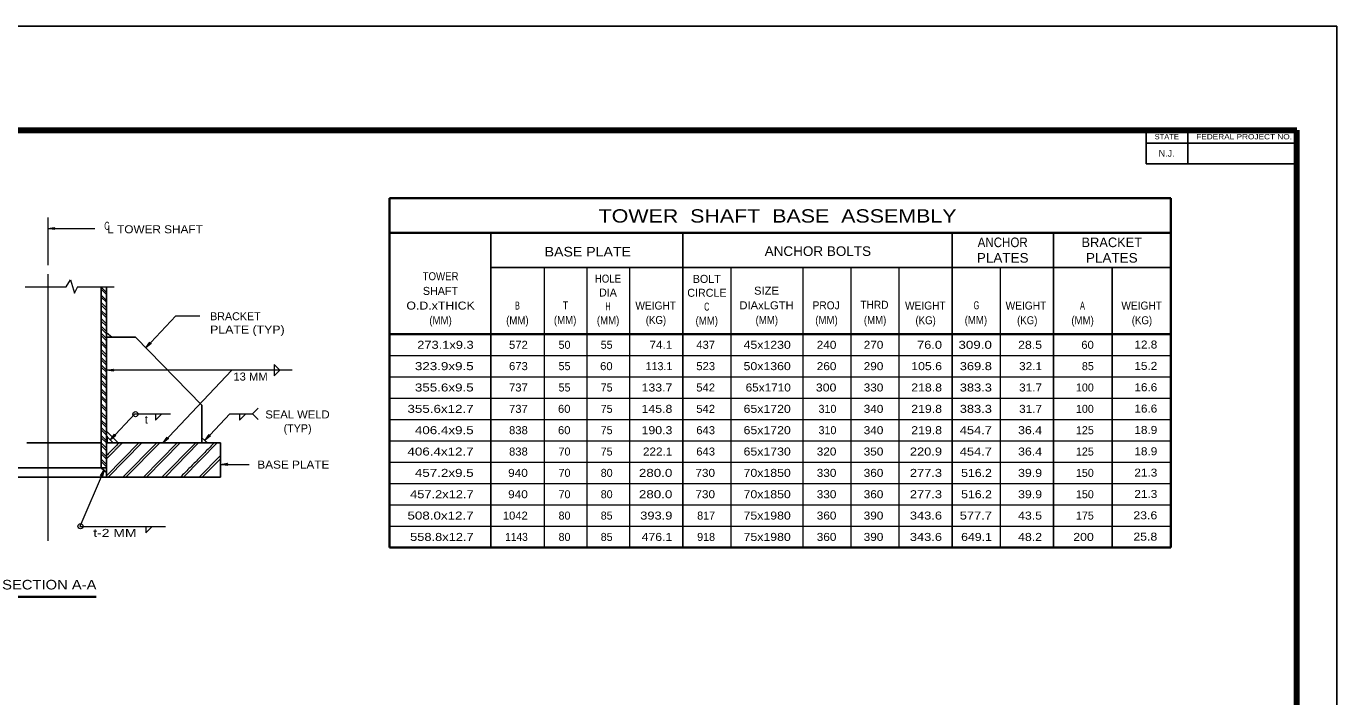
# Model space of a CAD drawing. Extents: x 312601.859 to 312602.7, y 144420.109 to 144420.704.
# Drawn here: x 312602.209 to 312602.7003, y 144420.4522 to 144420.7035 of the extents above; entities that cross this region are included whole.
import ezdxf
from ezdxf.enums import TextEntityAlignment as Align

# ---------------------------------------------------------------- set-up
doc = ezdxf.new("R2010")
doc.units = 0
doc.header["$LTSCALE"] = 0.0012
doc.linetypes.add('DOT_DASHED', pattern=[7.7, 5, -1.2, 0.3, -1.2])
doc.linetypes.add('LONG_DASHED', pattern=[7.5, 6, -1.5])
for name, color, linetype, lineweight in [('1', 7, 'Continuous', 13), ('2', 7, 'Continuous', 13), ('39', 7, 'Continuous', 13), ('61', 7, 'Continuous', 25)]:
    doc.layers.add(name, color=color, linetype=linetype, lineweight=lineweight)

msp = doc.modelspace()

# ---------------------------------------------------------------- hatches: boundary and pattern name
at = {"layer": '39'}
for points in [[(312602.2193, 144420.6277), (312602.2196, 144420.6273), (312602.217, 144420.6277), (312602.2196, 144420.6281)], [(312602.2554, 144420.5847), (312602.2558, 144420.5846), (312602.2538, 144420.583), (312602.2553, 144420.5851)], [(312602.2414, 144420.5746), (312602.2417, 144420.5742), (312602.2391, 144420.5746), (312602.2417, 144420.575)], [(312602.2421, 144420.5502), (312602.2425, 144420.5501), (312602.2405, 144420.5485), (312602.242, 144420.5506)], [(312602.2776, 144420.5501), (312602.278, 144420.55), (312602.276, 144420.5484), (312602.2775, 144420.5505)], [(312602.2619, 144420.5491), (312602.2623, 144420.549), (312602.2603, 144420.5474), (312602.2618, 144420.5495)], [(312602.2373, 144420.5351), (312602.2368, 144420.535), (312602.2382, 144420.5372), (312602.2375, 144420.5347)], [(312602.2841, 144420.5393), (312602.2844, 144420.5389), (312602.2818, 144420.5393), (312602.2844, 144420.5397)]]:
    msp.add_hatch(color=256, dxfattribs=at).paths.add_polyline_path(points)

# ---------------------------------------------------------------- linework, layer by layer
at = {"layer": '1', "lineweight": 35}
for p, q in [((312602.3451, 144420.6391), (312602.3451, 144420.5081)), ((312602.3451, 144420.6391), (312602.6381, 144420.6391)), ((312602.6381, 144420.6391), (312602.6381, 144420.5081)), ((312602.3451, 144420.6261), (312602.6381, 144420.6261)), ((312602.3451, 144420.5881), (312602.4555, 144420.5881)), ((312602.3451, 144420.5081), (312602.4555, 144420.5081)), ((312602.4551, 144420.5081), (312602.6381, 144420.5081))]:
    msp.add_line(p, q, dxfattribs=at)
at = {"layer": '1'}
for p, q in [((312602.217, 144420.6318), (312602.217, 144420.614)), ((312602.217, 144420.6277), (312602.2347, 144420.6277)), ((312602.4031, 144420.6131), (312602.4031, 144420.5081)), ((312602.4191, 144420.6131), (312602.4191, 144420.5081)), ((312602.4351, 144420.6131), (312602.4351, 144420.5081)), ((312602.4551, 144420.6131), (312602.4551, 144420.5081)), ((312602.4731, 144420.6131), (312602.4731, 144420.5081)), ((312602.5001, 144420.6131), (312602.5001, 144420.5081)), ((312602.5181, 144420.6131), (312602.5181, 144420.5081)), ((312602.5361, 144420.6131), (312602.5361, 144420.5081)), ((312602.5561, 144420.6131), (312602.5561, 144420.5081)), ((312602.5741, 144420.6131), (312602.5741, 144420.5081)), ((312602.2085, 144420.6058), (312602.2239, 144420.6058)), ((312602.2282, 144420.6058), (312602.2419, 144420.6058)), ((312602.237, 144420.6057), (312602.2391, 144420.6037)), ((312602.237, 144420.6049), (312602.2391, 144420.6029)), ((312602.2387, 144420.6058), (312602.2391, 144420.6054)), ((312602.237, 144420.6027), (312602.2391, 144420.6007)), ((312602.2391, 144420.5979), (312602.237, 144420.5999)), ((312602.2371, 144420.6019), (312602.2392, 144420.5999)), ((312602.2391, 144420.597), (312602.237, 144420.599)), ((312602.2391, 144420.5951), (312602.237, 144420.597)), ((312602.237, 144420.5962), (312602.2391, 144420.5942)), ((312602.2538, 144420.583), (312602.265, 144420.5949)), ((312602.265, 144420.5949), (312602.274, 144420.5949)), ((312602.2391, 144420.5919), (312602.237, 144420.5939)), ((312602.2391, 144420.5911), (312602.237, 144420.593)), ((312602.2391, 144420.5891), (312602.237, 144420.5911)), ((312602.2391, 144420.5882), (312602.237, 144420.5902)), ((312602.2391, 144420.5864), (312602.237, 144420.5885)), ((312602.2391, 144420.5856), (312602.237, 144420.5876)), ((312602.2391, 144420.5834), (312602.237, 144420.5855)), ((312602.2391, 144420.5826), (312602.237, 144420.5846)), ((312602.2391, 144420.5803), (312602.237, 144420.5823)), ((312602.2391, 144420.5794), (312602.237, 144420.5814)), ((312602.3451, 144420.5801), (312602.4555, 144420.5801)), ((312602.2391, 144420.5774), (312602.237, 144420.5794)), ((312602.2391, 144420.5765), (312602.237, 144420.5785)), ((312602.2391, 144420.5746), (312602.237, 144420.5766)), ((312602.2391, 144420.5738), (312602.237, 144420.5757)), ((312602.3086, 144420.5746), (312602.2391, 144420.5746)), ((312602.2603, 144420.5474), (312602.2861, 144420.5746)), ((312602.2391, 144420.5716), (312602.237, 144420.5736)), ((312602.2391, 144420.5708), (312602.237, 144420.5727)), ((312602.2391, 144420.5687), (312602.237, 144420.5708)), ((312602.2391, 144420.5679), (312602.237, 144420.5699)), ((312602.3451, 144420.5721), (312602.4555, 144420.5721)), ((312602.2391, 144420.5656), (312602.237, 144420.5676)), ((312602.2391, 144420.5648), (312602.237, 144420.5667)), ((312602.2391, 144420.563), (312602.237, 144420.565)), ((312602.2391, 144420.5622), (312602.237, 144420.5642)), ((312602.2391, 144420.56), (312602.237, 144420.562)), ((312602.2391, 144420.5591), (312602.237, 144420.5611)), ((312602.3451, 144420.5641), (312602.4555, 144420.5641)), ((312602.2391, 144420.5569), (312602.237, 144420.5588)), ((312602.2391, 144420.556), (312602.237, 144420.5579)), ((312602.2391, 144420.554), (312602.237, 144420.5559)), ((312602.2391, 144420.5531), (312602.237, 144420.5551)), ((312602.3451, 144420.5561), (312602.4555, 144420.5561)), ((312602.2391, 144420.5511), (312602.237, 144420.5531)), ((312602.2391, 144420.5502), (312602.237, 144420.5522)), ((312602.2391, 144420.5481), (312602.237, 144420.5501)), ((312602.2391, 144420.5473), (312602.237, 144420.5492)), ((312602.2391, 144420.5453), (312602.237, 144420.5473)), ((312602.2391, 144420.5444), (312602.237, 144420.5464)), ((312602.2512, 144420.5474), (312602.2391, 144420.535)), ((312602.2393, 144420.5498), (312602.2393, 144420.5474)), ((312602.2523, 144420.5474), (312602.2397, 144420.5345)), ((312602.2579, 144420.5474), (312602.2452, 144420.5345)), ((312602.2591, 144420.5474), (312602.2463, 144420.5345)), ((312602.2655, 144420.5474), (312602.2529, 144420.5345)), ((312602.2667, 144420.5474), (312602.254, 144420.5345)), ((312602.2725, 144420.5474), (312602.2598, 144420.5345)), ((312602.2736, 144420.5474), (312602.261, 144420.5345)), ((312602.2806, 144420.5474), (312602.2679, 144420.5345)), ((312602.3451, 144420.5481), (312602.4555, 144420.5481)), ((312602.2391, 144420.5421), (312602.237, 144420.5441)), ((312602.2391, 144420.5413), (312602.237, 144420.5432)), ((312602.2391, 144420.5393), (312602.237, 144420.5412)), ((312602.2391, 144420.5384), (312602.237, 144420.5404)), ((312602.2818, 144420.5426), (312602.2738, 144420.5345)), ((312602.2818, 144420.5414), (312602.2749, 144420.5345)), ((312602.237, 144420.538), (312602.2391, 144420.5362)), ((312602.2818, 144420.5393), (312602.2925, 144420.5393)), ((312602.3451, 144420.5401), (312602.4555, 144420.5401)), ((312602.3451, 144420.5321), (312602.4555, 144420.5321)), ((312602.3451, 144420.5241), (312602.4555, 144420.5241)), ((312602.2291, 144420.516), (312602.2612, 144420.516)), ((312602.3451, 144420.5161), (312602.4555, 144420.5161))]:
    msp.add_line(p, q, dxfattribs=at)
at = {"layer": '1', "lineweight": 25}
for p, q in [((312602.3831, 144420.6261), (312602.3831, 144420.5081)), ((312602.4551, 144420.6261), (312602.4551, 144420.5081)), ((312602.5561, 144420.6261), (312602.5561, 144420.5081)), ((312602.5941, 144420.6261), (312602.5941, 144420.5081)), ((312602.3831, 144420.6131), (312602.4555, 144420.6131)), ((312602.6161, 144420.6131), (312602.6161, 144420.5081)), ((312602.237, 144420.6058), (312602.237, 144420.538)), ((312602.2391, 144420.6058), (312602.2391, 144420.5345)), ((312602.2499, 144420.5869), (312602.2391, 144420.5869)), ((312602.2748, 144420.5615), (312602.2499, 144420.5869)), ((312602.2748, 144420.5615), (312602.2748, 144420.5474)), ((312602.2434, 144420.5474), (312602.2391, 144420.5517)), ((312602.2818, 144420.5474), (312602.2818, 144420.5345)), ((312602.1949, 144420.538), (312602.2391, 144420.538)), ((312602.1522, 144420.5345), (312602.2818, 144420.5345))]:
    msp.add_line(p, q, dxfattribs=at)
at = {"layer": '1', "linetype": 'DOT_DASHED'}
msp.add_line((312602.217, 144420.6106), (312602.217, 144420.5106), dxfattribs=at)
at = {"layer": '1', "linetype": 'LONG_DASHED', "lineweight": 25}
msp.add_line((312602.2092, 144420.5474), (312602.237, 144420.5474), dxfattribs=at)
at = {"layer": '1', "lineweight": 25}
msp.add_lwpolyline([(312602.4551, 144420.6131), (312602.5561, 144420.6131), (312602.6381, 144420.6131)], dxfattribs=at)
at = {"layer": '1'}
for points in [[(312602.2391, 144420.5869), (312602.2391, 144420.5887), (312602.2412, 144420.5869)], [(312602.2415, 144420.5474), (312602.2391, 144420.5498), (312602.2391, 144420.5474)], [(312602.2748, 144420.5474), (312602.2748, 144420.5492), (312602.2769, 144420.5474)], [(312602.2391, 144420.538), (312602.2391, 144420.5362), (312602.237, 144420.538)]]:
    msp.add_lwpolyline(points, close=True, dxfattribs=at)
at = {"layer": '1', "lineweight": 35}
msp.add_lwpolyline([(312602.4551, 144420.5881), (312602.5561, 144420.5881), (312602.6381, 144420.5881)], dxfattribs=at)
at = {"layer": '1'}
for points in [[(312602.4551, 144420.5801), (312602.5561, 144420.5801), (312602.6381, 144420.5801)], [(312602.4551, 144420.5721), (312602.5561, 144420.5721), (312602.6381, 144420.5721)], [(312602.4551, 144420.5641), (312602.5561, 144420.5641), (312602.6381, 144420.5641)], [(312602.2405, 144420.5485), (312602.2497, 144420.5582), (312602.2631, 144420.5582)], [(312602.276, 144420.5484), (312602.2853, 144420.5582), (312602.2938, 144420.5582)], [(312602.4551, 144420.5561), (312602.5561, 144420.5561), (312602.6381, 144420.5561)], [(312602.2415, 144420.5474), (312602.2391, 144420.5498), (312602.2391, 144420.5474)], [(312602.4551, 144420.5481), (312602.5561, 144420.5481), (312602.6381, 144420.5481)], [(312602.4551, 144420.5401), (312602.5561, 144420.5401), (312602.6381, 144420.5401)], [(312602.4551, 144420.5321), (312602.5561, 144420.5321), (312602.6381, 144420.5321)], [(312602.4551, 144420.5241), (312602.5561, 144420.5241), (312602.6381, 144420.5241)], [(312602.4551, 144420.5161), (312602.5561, 144420.5161), (312602.6381, 144420.5161)]]:
    msp.add_lwpolyline(points, dxfattribs=at)
at = {"layer": '1', "lineweight": 25}
msp.add_open_spline([(312602.2818, 144420.5474), (312602.2391, 144420.5474)], degree=1, dxfattribs=at)
at = {"layer": '1'}
for points in [[(312602.2438, 144420.5474), (312602.2391, 144420.5426)], [(312602.245, 144420.5474), (312602.2391, 144420.5414)], [(312602.2795, 144420.5474), (312602.2668, 144420.5345)]]:
    msp.add_open_spline(points, degree=1, dxfattribs=at)
at = {"layer": '2'}
for p, q in [((312602.2938, 144420.5582), (312602.2959, 144420.5603)), ((312602.2959, 144420.5561), (312602.2938, 144420.5582)), ((312602.2382, 144420.5372), (312602.2291, 144420.516))]:
    msp.add_line(p, q, dxfattribs=at)
at = {"layer": '2', "lineweight": 35}
msp.add_line((312602.2352, 144420.4896), (312602.1993, 144420.4896), dxfattribs=at)
at = {"layer": '2'}
for points in [[(312602.2239, 144420.6058), (312602.2256, 144420.6084), (312602.227, 144420.6034), (312602.2283, 144420.606)], [(312602.2574, 144420.5582), (312602.2574, 144420.5558), (312602.2598, 144420.5582)], [(312602.2889, 144420.5582), (312602.2889, 144420.5558), (312602.2913, 144420.5582)], [(312602.2538, 144420.516), (312602.2538, 144420.5136), (312602.2562, 144420.516)]]:
    msp.add_lwpolyline(points, dxfattribs=at)
msp.add_lwpolyline([(312602.304, 144420.5746), (312602.3019, 144420.5767), (312602.3019, 144420.5725)], close=True, dxfattribs=at)
for centre in [(312602.2499, 144420.5581), (312602.2293, 144420.5161)]:
    msp.add_circle(centre, 0.000949, dxfattribs=at)
at = {"layer": '39', "lineweight": 25}
for p, q in [((312601.8593, 144420.7035), (312602.7003, 144420.7035)), ((312602.575, 144420.6645), (312602.6853, 144420.6645)), ((312602.6853, 144420.6514), (312602.6853, 144420.6645))]:
    msp.add_line(p, q, dxfattribs=at)
msp.add_lwpolyline([(312601.8593, 144420.1095), (312602.7003, 144420.1095), (312602.7003, 144420.7035)], dxfattribs=at)
at = {"layer": '39', "lineweight": 158}
for points in [[(312601.9103, 144420.1245), (312602.6853, 144420.1245), (312602.6853, 144420.6645)], [(312601.9103, 144420.1247), (312601.9103, 144420.6645), (312602.6853, 144420.6645)]]:
    msp.add_lwpolyline(points, dxfattribs=at)
at = {"layer": '39'}
for points in [[(312602.2193, 144420.6277), (312602.2196, 144420.6273), (312602.217, 144420.6277), (312602.2196, 144420.6281)], [(312602.2554, 144420.5847), (312602.2558, 144420.5846), (312602.2538, 144420.583), (312602.2553, 144420.5851)], [(312602.2414, 144420.5746), (312602.2417, 144420.5742), (312602.2391, 144420.5746), (312602.2417, 144420.575)], [(312602.2421, 144420.5502), (312602.2425, 144420.5501), (312602.2405, 144420.5485), (312602.242, 144420.5506)], [(312602.2776, 144420.5501), (312602.278, 144420.55), (312602.276, 144420.5484), (312602.2775, 144420.5505)], [(312602.2619, 144420.5491), (312602.2623, 144420.549), (312602.2603, 144420.5474), (312602.2618, 144420.5495)], [(312602.2373, 144420.5351), (312602.2368, 144420.535), (312602.2382, 144420.5372), (312602.2375, 144420.5347)], [(312602.2841, 144420.5393), (312602.2844, 144420.5389), (312602.2818, 144420.5393), (312602.2844, 144420.5397)]]:
    msp.add_lwpolyline(points, close=True, dxfattribs=at)
at = {"layer": '61'}
for p, q in [((312602.6288, 144420.6645), (312602.6288, 144420.6519)), ((312602.6444, 144420.6645), (312602.6444, 144420.6519)), ((312602.6853, 144420.6597), (312602.6288, 144420.6597)), ((312602.6853, 144420.6519), (312602.6288, 144420.6519))]:
    msp.add_line(p, q, dxfattribs=at)

# ---------------------------------------------------------------- texts
at = {"layer": '2'}
for s, height, width, p in [('TOWER  SHAFT  BASE  ASSEMBLY', 0.005, 1.2, (312602.49065, 144420.6299)), ('C', 0.003, 0.6, (312602.2392, 144420.6272)), ('L TOWER SHAFT', 0.003, 1.1, (312602.25725, 144420.6259)), ('ANCHOR', 0.0036, 0.9, (312602.57505, 144420.6207)), ('BASE PLATE', 0.0036, 1.1, (312602.4195, 144420.6172)), ('ANCHOR BOLTS', 0.0036, 1.05, (312602.50575, 144420.6174)), ('PLATES', 0.0036, 1.05, (312602.57505, 144420.6149)), ('PLATES', 0.0036, 1.05, (312602.61595, 144420.6149)), ('TOWER', 0.003, 0.9, (312602.3643, 144420.6083)), ('HOLE', 0.003, 0.9, (312602.42705, 144420.6074)), ('SIZE', 0.003, 1.05, (312602.4865, 144420.6029)), ('O.D.xTHICK', 0.003, 1.15, (312602.3643, 144420.5973)), ('B', 0.003, 0.7, (312602.3931, 144420.5973)), ('T', 0.003, 0.8, (312602.41115, 144420.5974)), ('H', 0.003, 0.6, (312602.42705, 144420.597)), ('WEIGHT', 0.003, 0.95, (312602.44495, 144420.5973)), ('C', 0.003, 0.6, (312602.4641, 144420.5969)), ('DIAxLGTH', 0.003, 1.05, (312602.4865, 144420.5974)), ('PROJ', 0.003, 0.95, (312602.50885, 144420.5974)), ('THRD', 0.003, 0.95, (312602.52695, 144420.5976)), ('WEIGHT', 0.003, 0.95, (312602.54605, 144420.5973)), ('G', 0.003, 0.6, (312602.5652, 144420.5974)), ('WEIGHT', 0.003, 0.95, (312602.58375, 144420.5973)), ('A', 0.003, 0.7, (312602.60495, 144420.5973)), ('WEIGHT', 0.003, 0.95, (312602.62715, 144420.5973)), ('(MM)', 0.003, 0.9, (312602.3643, 144420.5918)), ('(MM)', 0.003, 0.9, (312602.3931, 144420.5918)), ('(MM)', 0.003, 0.9, (312602.411, 144420.5919)), ('(MM)', 0.003, 0.9, (312602.4271, 144420.5918)), ('(KG)', 0.003, 0.9, (312602.44505, 144420.5919)), ('(MM)', 0.003, 0.9, (312602.4641, 144420.5917)), ('(MM)', 0.003, 0.9, (312602.4866, 144420.5919)), ('(MM)', 0.003, 0.9, (312602.509, 144420.5919)), ('(MM)', 0.003, 0.9, (312602.5272, 144420.5919)), ('(KG)', 0.003, 0.9, (312602.54615, 144420.5918)), ('(MM)', 0.003, 0.9, (312602.565, 144420.5919)), ('(KG)', 0.003, 0.9, (312602.58425, 144420.5918)), ('(MM)', 0.003, 0.9, (312602.605, 144420.5918)), ('(KG)', 0.003, 0.9, (312602.62725, 144420.5918)), ('13 MM', 0.003, 1.05, (312602.29305, 144420.5707)), ('SEAL WELD', 0.003, 1.05, (312602.31065, 144420.5565)), ('BASE PLATE', 0.003, 1.1, (312602.3091, 144420.5377)), ('t-2 MM', 0.003, 1.3, (312602.2422, 144420.5121)), ('SECTION A-A', 0.0036, 1.15, (312602.2176, 144420.4924))]:
    msp.add_text(s, height=height, dxfattribs=dict(at, width=width)).set_placement(p, align=Align.CENTER)
for s, height, p in [('BRACKET', 0.0036, (312602.61595, 144420.6207)), ('BOLT', 0.003, (312602.4641, 144420.6073)), ('SHAFT', 0.003, (312602.36425, 144420.6028)), ('DIA', 0.003, (312602.42705, 144420.6022)), ('CIRCLE', 0.003, (312602.46415, 144420.6021)), ('t', 0.003, (312602.25395, 144420.5546)), ('(TYP)', 0.003, (312602.3107, 144420.5513))]:
    msp.add_text(s, height=height, dxfattribs=at).set_placement(p, align=Align.CENTER)
msp.add_text('BRACKET', height=0.003, dxfattribs=at).set_placement((312602.2779, 144420.5933))
at = {"layer": '2', "width": 1.15}
msp.add_text('PLATE (TYP)', height=0.003, dxfattribs=at).set_placement((312602.2779, 144420.5883))
at = {"layer": '2'}
for s, width, p in [('273.1x9.3', 1.2, (312602.3767, 144420.5826)), ('572', 1.05, (312602.397, 144420.5826)), ('74.1', 1.1, (312602.4512, 144420.5826)), ('437', 1.05, (312602.4672, 144420.5826)), ('45x1230', 1.15, (312602.4956, 144420.5826)), ('240', 1.1, (312602.5127, 144420.5826)), ('270', 1.1, (312602.5303, 144420.5826)), ('76.0', 1.2, (312602.5523, 144420.5826)), ('309.0', 1.25, (312602.571, 144420.5826)), ('28.5', 1.15, (312602.5898, 144420.5826)), ('60', 1.05, (312602.6092, 144420.5826)), ('12.8', 1.1, (312602.633, 144420.5827)), ('323.9x9.5', 1.25, (312602.3767, 144420.5746)), ('673', 1.05, (312602.397, 144420.5746)), ('60', 1.05, (312602.4288, 144420.5746)), ('523', 1.05, (312602.4672, 144420.5746)), ('50x1360', 1.15, (312602.4956, 144420.5746)), ('260', 1.1, (312602.5127, 144420.5746)), ('290', 1.1, (312602.5303, 144420.5746)), ('105.6', 1.15, (312602.5523, 144420.5746)), ('369.8', 1.2, (312602.571, 144420.5746)), ('32.1', 1.1, (312602.5898, 144420.5746)), ('15.2', 1.1, (312602.633, 144420.5747)), ('355.6x9.5', 1.25, (312602.3767, 144420.5666)), ('737', 1.05, (312602.397, 144420.5666)), ('133.7', 1.15, (312602.4512, 144420.5666)), ('542', 1.05, (312602.4672, 144420.5666)), ('65x1710', 1.1, (312602.4956, 144420.5666)), ('300', 1.15, (312602.5127, 144420.5666)), ('330', 1.1, (312602.5303, 144420.5666)), ('218.8', 1.15, (312602.5523, 144420.5666)), ('383.3', 1.2, (312602.571, 144420.5666)), ('31.7', 1.1, (312602.5898, 144420.5666)), ('16.6', 1.1, (312602.633, 144420.5667)), ('355.6x12.7', 1.25, (312602.3767, 144420.5586)), ('737', 1.05, (312602.397, 144420.5586)), ('60', 1.05, (312602.413, 144420.5586)), ('145.8', 1.15, (312602.4512, 144420.5586)), ('542', 1.05, (312602.4672, 144420.5586)), ('65x1720', 1.15, (312602.4956, 144420.5586)), ('340', 1.1, (312602.5303, 144420.5586)), ('219.8', 1.15, (312602.5523, 144420.5586)), ('383.3', 1.2, (312602.571, 144420.5586)), ('31.7', 1.1, (312602.5898, 144420.5586)), ('16.6', 1.1, (312602.633, 144420.5587)), ('406.4x9.5', 1.25, (312602.3767, 144420.5506)), ('838', 1.05, (312602.397, 144420.5506)), ('60', 1.05, (312602.413, 144420.5506)), ('190.3', 1.15, (312602.4512, 144420.5506)), ('643', 1.05, (312602.4672, 144420.5506)), ('65x1720', 1.15, (312602.4956, 144420.5506)), ('340', 1.1, (312602.5303, 144420.5506)), ('219.8', 1.15, (312602.5523, 144420.5506)), ('454.7', 1.2, (312602.571, 144420.5506)), ('36.4', 1.15, (312602.5898, 144420.5506)), ('18.9', 1.1, (312602.633, 144420.5507)), ('406.4x12.7', 1.25, (312602.3767, 144420.5426)), ('838', 1.05, (312602.397, 144420.5426)), ('222.1', 1.1, (312602.4512, 144420.5426)), ('643', 1.05, (312602.4672, 144420.5426)), ('65x1730', 1.15, (312602.4956, 144420.5426)), ('320', 1.1, (312602.5127, 144420.5426)), ('350', 1.1, (312602.5303, 144420.5426)), ('220.9', 1.2, (312602.5523, 144420.5426)), ('454.7', 1.2, (312602.571, 144420.5426)), ('36.4', 1.15, (312602.5898, 144420.5426)), ('18.9', 1.1, (312602.633, 144420.5427)), ('457.2x9.5', 1.25, (312602.3767, 144420.5346)), ('940', 1.1, (312602.397, 144420.5346)), ('280.0', 1.25, (312602.4512, 144420.5346)), ('730', 1.1, (312602.4672, 144420.5346)), ('70x1850', 1.15, (312602.4956, 144420.5346)), ('330', 1.1, (312602.5127, 144420.5346)), ('360', 1.1, (312602.5303, 144420.5346)), ('277.3', 1.2, (312602.5523, 144420.5346)), ('516.2', 1.15, (312602.571, 144420.5346)), ('39.9', 1.15, (312602.5898, 144420.5346)), ('21.3', 1.1, (312602.633, 144420.5347)), ('457.2x12.7', 1.2, (312602.3767, 144420.5266)), ('940', 1.1, (312602.397, 144420.5266)), ('280.0', 1.25, (312602.4512, 144420.5266)), ('730', 1.1, (312602.4672, 144420.5266)), ('70x1850', 1.15, (312602.4956, 144420.5266)), ('330', 1.1, (312602.5127, 144420.5266)), ('360', 1.1, (312602.5303, 144420.5266)), ('277.3', 1.2, (312602.5523, 144420.5266)), ('516.2', 1.15, (312602.571, 144420.5266)), ('39.9', 1.15, (312602.5898, 144420.5266)), ('21.3', 1.1, (312602.633, 144420.5267)), ('508.0x12.7', 1.25, (312602.3767, 144420.5186)), ('1042', 1.05, (312602.397, 144420.5186)), ('393.9', 1.2, (312602.4512, 144420.5186)), ('75x1980', 1.15, (312602.4956, 144420.5186)), ('360', 1.1, (312602.5127, 144420.5186)), ('390', 1.1, (312602.5303, 144420.5186)), ('343.6', 1.2, (312602.5523, 144420.5186)), ('577.7', 1.2, (312602.571, 144420.5186)), ('43.5', 1.15, (312602.5898, 144420.5186)), ('23.6', 1.15, (312602.633, 144420.5187)), ('558.8x12.7', 1.2, (312602.3767, 144420.5106)), ('1143', 0.95, (312602.397, 144420.5106)), ('476.1', 1.15, (312602.4512, 144420.5106)), ('75x1980', 1.15, (312602.4956, 144420.5106)), ('360', 1.1, (312602.5127, 144420.5106)), ('390', 1.1, (312602.5303, 144420.5106)), ('343.6', 1.2, (312602.5523, 144420.5106)), ('649.1', 1.15, (312602.571, 144420.5106)), ('48.2', 1.15, (312602.5898, 144420.5106)), ('200', 1.15, (312602.6092, 144420.5106)), ('25.8', 1.15, (312602.633, 144420.5107))]:
    msp.add_text(s, height=0.003, dxfattribs=dict(at, width=width)).set_placement(p, align=Align.RIGHT)
for s, p in [('50', (312602.413, 144420.5826)), ('55', (312602.4288, 144420.5826)), ('55', (312602.413, 144420.5746)), ('113.1', (312602.4512, 144420.5746)), ('85', (312602.6092, 144420.5746)), ('55', (312602.413, 144420.5666)), ('75', (312602.4288, 144420.5666)), ('100', (312602.6092, 144420.5666)), ('75', (312602.4288, 144420.5586)), ('310', (312602.5127, 144420.5586)), ('100', (312602.6092, 144420.5586)), ('75', (312602.4288, 144420.5506)), ('310', (312602.5127, 144420.5506)), ('125', (312602.6092, 144420.5506)), ('70', (312602.413, 144420.5426)), ('75', (312602.4288, 144420.5426)), ('125', (312602.6092, 144420.5426)), ('70', (312602.413, 144420.5346)), ('80', (312602.4288, 144420.5346)), ('150', (312602.6092, 144420.5346)), ('70', (312602.413, 144420.5266)), ('80', (312602.4288, 144420.5266)), ('150', (312602.6092, 144420.5266)), ('80', (312602.413, 144420.5186)), ('85', (312602.4288, 144420.5186)), ('817', (312602.4672, 144420.5186)), ('175', (312602.6092, 144420.5186)), ('80', (312602.413, 144420.5106)), ('85', (312602.4288, 144420.5106)), ('918', (312602.4672, 144420.5106))]:
    msp.add_text(s, height=0.003, dxfattribs=at).set_placement(p, align=Align.RIGHT)
at = {"layer": '61'}
for s, width, p in [('STATE', 1.05, (312602.63655, 144420.6611)), ('FEDERAL PROJECT NO.', 1.15, (312602.66555, 144420.6611))]:
    msp.add_text(s, height=0.00201, dxfattribs=dict(at, width=width)).set_placement(p, align=Align.CENTER)
msp.add_text('N.J.', height=0.002512, dxfattribs=at).set_placement((312602.6365, 144420.6546), align=Align.CENTER)

doc.saveas('drawing.dxf')
